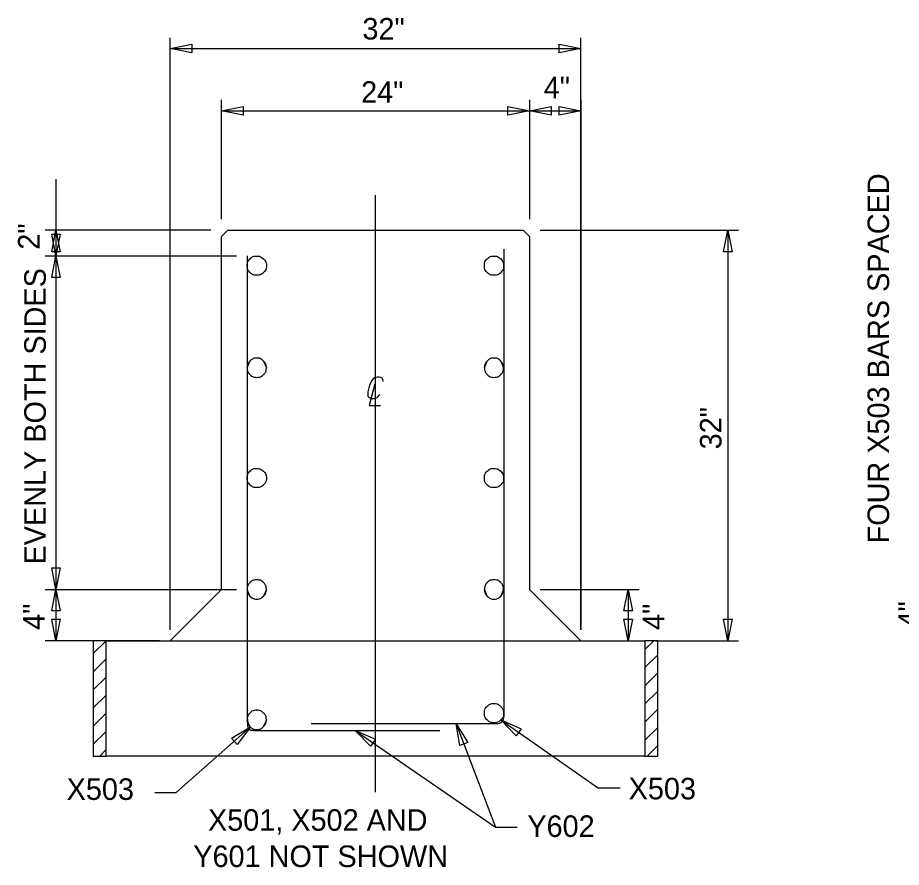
# Model space of a CAD drawing. Extents: x 0 to 680, y 0 to 440.
# Drawn here: x 288.1 to 402.6, y 192.8 to 302.9 of the extents above; entities that cross this region are included whole.
import ezdxf

# ---------------------------------------------------------------- set-up
doc = ezdxf.new("R2010")
doc.units = 0
doc.layers.add('Default', color=7, linetype='Continuous')

msp = doc.modelspace()

# ---------------------------------------------------------------- linework, layer by layer
at = {"layer": 'Default'}
for p, q in [((307.9, 223.56), (307.9, 300.29)), ((307.9, 298.87), (361.1, 298.87)), ((314.55, 276.76), (314.55, 292.22)), ((354.45, 292.22), (354.45, 276.76)), ((293.1, 281.97), (293.1, 275.35)), ((334.5, 202.53), (334.5, 279.89)), ((313.17, 275.35), (291.72, 275.35)), ((355.84, 275.35), (381.55, 275.35)), ((380.17, 275.35), (380.17, 222.15)), ((351.13, 272.88), (351.13, 212.23)), ((291.72, 272.02), (316.49, 272.02)), ((317.88, 257.53), (318.24, 258.39)), ((320.01, 258.39), (320.37, 257.53)), ((348.61, 257.53), (348.97, 258.39)), ((350.74, 258.39), (351.1, 257.53)), ((291.72, 228.8), (316.49, 228.8)), ((318.24, 227.94), (317.88, 228.8)), ((320.37, 228.8), (320.01, 227.94)), ((348.97, 227.94), (348.61, 228.8)), ((351.1, 228.8), (350.74, 227.94)), ((355.84, 228.8), (368.67, 228.8)), ((367.26, 228.8), (367.26, 222.15)), ((306.52, 222.15), (291.72, 222.15)), ((307.9, 222.15), (361.1, 222.15)), ((362.49, 222.15), (368.67, 222.15)), ((369.42, 221.01), (370.55, 222.15)), ((370.8, 222.15), (381.55, 222.15)), ((371.07, 220.34), (369.42, 218.68)), ((299.59, 219.79), (297.93, 218.13)), ((371.07, 217.98), (369.42, 216.33)), ((299.59, 217.43), (297.93, 215.78)), ((371.07, 215.63), (369.42, 213.97)), ((299.59, 215.11), (297.93, 213.45)), ((371.07, 213.27), (369.42, 211.62)), ((299.59, 212.75), (297.93, 211.09)), ((318.24, 211.03), (317.88, 211.89)), ((320.37, 211.89), (320.01, 211.03)), ((350.74, 211.89), (363.4, 203.03)), ((318.29, 210.98), (308.7, 202.47)), ((350.3, 211.39), (326.19, 211.39)), ((344.95, 211.39), (350.05, 197.98)), ((371.07, 210.92), (369.42, 209.26)), ((299.59, 210.4), (297.93, 208.74)), ((331.87, 210.51), (350.05, 197.98)), ((371.07, 208.56), (369.71, 207.2)), ((299.59, 208.04), (298.77, 207.2)), ((366.2, 203.03), (363.4, 203.03)), ((305.91, 202.47), (308.7, 202.47)), ((350.05, 197.98), (352.85, 197.98))]:
    msp.add_line(p, q, dxfattribs=at)
for points in [[(361.1, 292.22), (361.1, 223.56), (361.1, 300.29)], [(314.55, 290.81), (354.45, 290.81), (361.1, 290.81)], [(293.1, 275.35), (293.1, 272.02), (293.1, 228.8), (293.1, 222.15)], [(299.59, 222.15), (307.9, 222.15), (314.55, 228.8), (314.55, 274.52), (315.38, 275.35), (353.62, 275.35), (354.45, 274.52), (354.45, 228.8), (361.1, 222.15), (369.42, 222.15), (369.42, 207.18), (299.59, 207.18), (299.59, 222.15), (297.93, 220.49)], [(335.5, 255.76), (335.47, 256.01), (335.39, 256.15), (335.31, 256.23), (335.25, 256.28), (335, 256.31), (334.75, 256.31), (334.42, 256.23), (334.2, 256.09), (333.98, 255.84), (333.75, 255.37), (333.64, 254.93), (333.53, 254.4), (333.5, 254.07), (333.5, 253.98), (333.53, 253.85), (333.59, 253.76), (333.64, 253.71), (333.75, 253.62), (333.86, 253.57), (334, 253.54), (334.2, 253.54), (334.39, 253.54), (334.5, 253.57), (334.59, 253.62), (334.7, 253.68), (334.83, 253.82), (334.95, 253.93), (335.06, 254.07)], [(334.42, 255.45), (333.67, 252.65), (335.17, 252.65)]]:
    msp.add_lwpolyline(points, dxfattribs=at)
for points in [[(310.7, 298.32), (307.9, 298.87), (310.7, 299.43)], [(358.3, 299.43), (361.1, 298.87), (358.3, 298.32)], [(317.35, 290.26), (314.55, 290.81), (317.35, 291.39)], [(351.65, 291.39), (354.45, 290.81), (351.65, 290.26)], [(357.25, 290.26), (354.45, 290.81), (357.25, 291.39)], [(358.3, 291.39), (361.1, 290.81), (358.3, 290.26)], [(292.55, 272.55), (293.1, 275.35), (293.66, 272.55)], [(293.66, 274.82), (293.1, 272.02), (292.55, 274.82)], [(379.61, 272.55), (380.17, 275.35), (380.72, 272.55)], [(292.55, 269.22), (293.1, 272.02), (293.66, 269.22)], [(293.66, 231.59), (293.1, 228.8), (292.55, 231.59)], [(292.55, 226.02), (293.1, 228.8), (293.66, 226.02)], [(366.7, 226.02), (367.26, 228.8), (367.81, 226.02)], [(293.66, 224.94), (293.1, 222.15), (292.55, 224.94)], [(367.81, 224.94), (367.26, 222.15), (366.7, 224.94)], [(380.72, 224.94), (380.17, 222.15), (379.61, 224.94)], [(299.59, 207.18), (299.59, 222.15), (297.93, 222.15), (297.93, 207.18)], [(371.08, 207.18), (371.08, 222.15), (369.42, 222.15), (369.42, 207.18)], [(352.71, 209.84), (350.74, 211.89), (353.37, 210.76)], [(315.83, 209.54), (318.29, 210.98), (316.57, 208.71)], [(345.42, 208.57), (344.95, 211.39), (346.47, 208.98)], [(333.86, 208.48), (331.87, 210.51), (334.5, 209.4)]]:
    msp.add_lwpolyline(points, close=True, dxfattribs=at)
for centre, radius, start, end in [((319.09, 257.53), 1.22, 134.723, 179.7751), ((319.15, 257.53), 1.22, 0.2249, 45.277), ((349.82, 257.53), 1.22, 134.723, 179.7751), ((349.88, 257.53), 1.22, 0.2249, 45.277), ((319.09, 228.8), 1.22, 180.2249, 225.277), ((319.15, 228.8), 1.22, 314.723, 359.7751), ((349.82, 228.8), 1.22, 180.2249, 225.277), ((349.88, 228.8), 1.22, 314.723, 359.7751), ((319.09, 211.9), 1.22, 180.2249, 225.277), ((319.15, 211.9), 1.22, 314.723, 359.7751), ((350.29, 212.23), 0.834, 270.1626, 359.838)]:
    msp.add_arc(centre, radius, start, end, dxfattribs=at)
for points, degree in [([(317.88, 272.02), (317.88, 251.79), (317.88, 231.57), (317.88, 211.34), (317.88, 210.9), (318.26, 210.51), (318.71, 210.51), (326.74, 210.51), (334.78, 210.51), (342.82, 210.51)], 4), ([(320.01, 271.63), (319.76, 271.86), (319.46, 272), (319.12, 272), (318.79, 272), (318.49, 271.86), (318.24, 271.63), (318.01, 271.39), (317.88, 271.08), (317.88, 270.75), (317.88, 270.42), (318.01, 270.11), (318.24, 269.86), (318.49, 269.64), (318.79, 269.5), (319.12, 269.5), (319.46, 269.5), (319.76, 269.64), (320.01, 269.86), (320.23, 270.11), (320.37, 270.42), (320.37, 270.75), (320.37, 271.08), (320.23, 271.39), (320.01, 271.63)], 3), ([(350.74, 271.63), (350.52, 271.86), (350.19, 272), (349.85, 272), (349.52, 272), (349.22, 271.86), (348.97, 271.63), (348.75, 271.39), (348.61, 271.08), (348.61, 270.75), (348.61, 270.42), (348.75, 270.11), (348.97, 269.86), (349.22, 269.64), (349.52, 269.5), (349.85, 269.5), (350.19, 269.5), (350.52, 269.64), (350.74, 269.86), (350.96, 270.11), (351.1, 270.42), (351.1, 270.75), (351.1, 271.08), (350.96, 271.39), (350.74, 271.63)], 3), ([(320.01, 258.39), (319.76, 258.64), (319.46, 258.78), (319.12, 258.78), (318.79, 258.78), (318.49, 258.64), (318.24, 258.39)], 3), ([(350.74, 258.39), (350.52, 258.64), (350.19, 258.78), (349.85, 258.78), (349.52, 258.78), (349.22, 258.64), (348.97, 258.39)], 3), ([(317.88, 257.53), (317.88, 257.2), (318.01, 256.87), (318.24, 256.64), (318.49, 256.39), (318.79, 256.28), (319.12, 256.28), (319.46, 256.28), (319.76, 256.39), (320.01, 256.64), (320.23, 256.87), (320.37, 257.2), (320.37, 257.53)], 3), ([(348.61, 257.53), (348.61, 257.2), (348.75, 256.87), (348.97, 256.64), (349.22, 256.39), (349.52, 256.28), (349.85, 256.28), (350.19, 256.28), (350.52, 256.39), (350.74, 256.64), (350.96, 256.87), (351.1, 257.2), (351.1, 257.53)], 3), ([(320.01, 244.12), (319.76, 244.34), (319.46, 244.48), (319.12, 244.48), (318.79, 244.48), (318.49, 244.34), (318.24, 244.12), (318.01, 243.87), (317.88, 243.56), (317.88, 243.23), (317.88, 242.9), (318.01, 242.57), (318.24, 242.35), (318.49, 242.12), (318.79, 241.99), (319.12, 241.99), (319.46, 241.99), (319.76, 242.12), (320.01, 242.35), (320.23, 242.57), (320.37, 242.9), (320.37, 243.23), (320.37, 243.56), (320.23, 243.87), (320.01, 244.12)], 3), ([(350.74, 244.12), (350.52, 244.34), (350.19, 244.48), (349.85, 244.48), (349.52, 244.48), (349.22, 244.34), (348.97, 244.12), (348.75, 243.87), (348.61, 243.56), (348.61, 243.23), (348.61, 242.9), (348.75, 242.57), (348.97, 242.35), (349.22, 242.12), (349.52, 241.99), (349.85, 241.99), (350.19, 241.99), (350.52, 242.12), (350.74, 242.35), (350.96, 242.57), (351.1, 242.9), (351.1, 243.23), (351.1, 243.56), (350.96, 243.87), (350.74, 244.12)], 3), ([(320.37, 228.8), (320.37, 229.13), (320.23, 229.46), (320.01, 229.68), (319.76, 229.93), (319.46, 230.04), (319.12, 230.04), (318.79, 230.04), (318.49, 229.93), (318.24, 229.68), (318.01, 229.46), (317.88, 229.13), (317.88, 228.8)], 3), ([(351.1, 228.8), (351.1, 229.13), (350.96, 229.46), (350.74, 229.68), (350.52, 229.93), (350.19, 230.04), (349.85, 230.04), (349.52, 230.04), (349.22, 229.93), (348.97, 229.68), (348.75, 229.46), (348.61, 229.13), (348.61, 228.8)], 3), ([(318.24, 227.94), (318.49, 227.69), (318.79, 227.55), (319.12, 227.55), (319.46, 227.55), (319.76, 227.69), (320.01, 227.94)], 3), ([(348.97, 227.94), (349.22, 227.69), (349.52, 227.55), (349.85, 227.55), (350.19, 227.55), (350.52, 227.69), (350.74, 227.94)], 3), ([(320.37, 211.89), (320.37, 212.23), (320.23, 212.56), (320.01, 212.78), (319.76, 213.03), (319.46, 213.14), (319.12, 213.14), (318.79, 213.14), (318.49, 213.03), (318.24, 212.78), (318.01, 212.56), (317.88, 212.23), (317.88, 211.89)], 3), ([(350.74, 213.64), (350.52, 213.89), (350.19, 214.03), (349.85, 214.03), (349.52, 214.03), (349.22, 213.89), (348.97, 213.64), (348.75, 213.42), (348.61, 213.08), (348.61, 212.78), (348.61, 212.45), (348.75, 212.11), (348.97, 211.89), (349.22, 211.64), (349.52, 211.53), (349.85, 211.53), (350.19, 211.53), (350.52, 211.64), (350.74, 211.89), (350.96, 212.11), (351.1, 212.45), (351.1, 212.78), (351.1, 213.08), (350.96, 213.42), (350.74, 213.64)], 3), ([(318.24, 211.03), (318.49, 210.78), (318.79, 210.65), (319.12, 210.65), (319.46, 210.65), (319.76, 210.78), (320.01, 211.03)], 3)]:
    msp.add_open_spline(points, degree=degree, dxfattribs=at)

# ---------------------------------------------------------------- texts
for s, height, p in [('32"', 2.793, (332.81, 300.05)), ('24"', 2.793, (332.64, 291.85)), ('4"', 2.793, (356.3, 292.43)), ('X503', 2.793, (294.49, 201.53)), ('X503', 2.793, (367.31, 201.6)), ('X501, X502 AND', 2.7931, (312.8, 197.53)), ('Y602', 2.793, (354.18, 196.73)), ('Y601 NOT SHOWN', 2.7931, (310.9, 192.83))]:
    msp.add_text(s, height=height, dxfattribs=at).set_placement(p)
for s, height, p in [('FOUR X503 BARS SPACED', 2.7931, (401.05, 234.76)), ('2"', 2.793, (290.98, 272.82)), ('EVENLY BOTH SIDES', 2.7931, (291.79, 232.03)), ('32"', 2.793, (379.33, 246.95)), ('4"', 2.793, (291.62, 223.56)), ('4"', 2.793, (371.93, 223.55)), ('4"', 2.793, (405.04, 223.87))]:
    msp.add_text(s, height=height, rotation=90, dxfattribs=at).set_placement(p)

doc.saveas('drawing.dxf')
